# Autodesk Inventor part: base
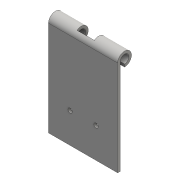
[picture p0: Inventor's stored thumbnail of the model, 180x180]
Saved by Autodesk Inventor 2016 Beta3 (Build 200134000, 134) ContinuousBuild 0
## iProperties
Created: 2016-03
Part Number: base
Material: Generic
Document SubType Name: Modeling
Designer: Gaurav
Density: 1 g/cm^3
Appearance: Default
Author: Gaurav
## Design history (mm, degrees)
sketch "Sketch1"
  geometry: L1 (0, 0)-(0, 50); L2 (0, 50)-(8, 50); L3 (8, 42)-(8, 50); L4 (3, 50)-(3, 0); L5 (8, 45)-(8, 42); L6 (3, 0)-(3, -60); L7 (3, -60)-(0, -60); L8 (0, -60)-(0, 0); A1 r 8 centre (8, 50) between (8, 42) and (0, 50); A2 r 5 centre (8, 50) between (8, 45) and (3, 50)
  constraints: 16 end point, 4 point on circle, 3 vertical, 2 centre point, 2 perpendicular, 1 collinear, 1 point on line, 1 tangent
  dimensions: "d0" = 50 distance of L1.start L1.end; "d1" = 8 radius of A1; "d2" = 90 deg angle of L2 L3; "d4" = 3 radial gap between concentric circles of A1 A2; "d7" = 60 distance of L4.end L6.end
extrude "Extrusion1" new body sketch "Sketch1" distance "d5" = 80; taper "d6" = 0 deg
sketch "Sketch2"
  geometry: L1 (30, 19.869)-(50, 19.869); L2 (50, 19.869)-(50, -19.869); L3 (50, -19.869)-(30, -19.869); L4 (30, -19.869)-(30, 19.869); L5 (0, 0)-(80, 0) reference; L6 (30, 19.869)-(50, -19.869); L7 (50, 19.869)-(30, -19.869); 2 further points
  constraints: 12 end point, 3 midpoint, 2 parallel, 1 horizontal, 1 perpendicular
  dimensions: "d8" = 20 distance of L2.end L3.end
extrude "Extrusion2" cut sketch "Sketch2" distance "d9" = 23.25; taper "d10" = 0 deg
hole "Hole1" diameter "d13" = 5; stored, may be unused: countersink angle "d17" = 90 deg, drill point angle "d19" = 118 deg; dims "d11" = 25, "d12" = 35, "d14" = 6, "d15" = 4, "d16" = 2, "d18" = 8
hole "Hole2" diameter "d22" = 5; stored, may be unused: countersink angle "d26" = 90 deg, drill point angle "d28" = 118 deg; dims "d20" = 25, "d21" = 35, "d23" = 6, "d24" = 4, "d25" = 2, "d27" = 8
body "Solid1"
